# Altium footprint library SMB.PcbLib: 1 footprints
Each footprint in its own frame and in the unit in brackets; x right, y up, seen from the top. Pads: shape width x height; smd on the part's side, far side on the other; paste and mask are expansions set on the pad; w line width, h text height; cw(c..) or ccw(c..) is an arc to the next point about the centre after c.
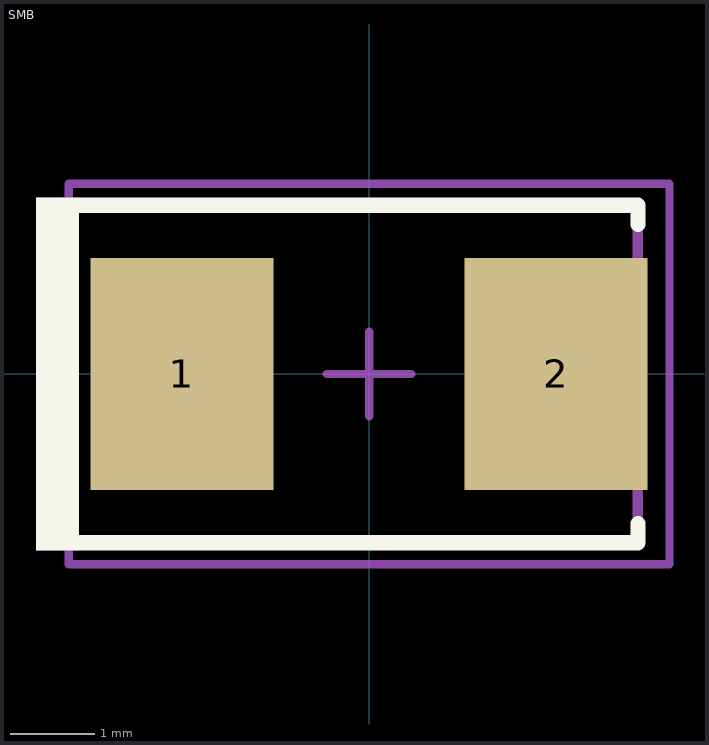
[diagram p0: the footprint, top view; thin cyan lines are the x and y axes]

## SMB [mil] "Molded Diode, 2-Leads, Body 5.4x3.6mm, IPC Medium Density, based on OnSemi component dimensions"
height 96.46
pads (2):
  rect 85x107.99 smd: 1(-87.01,0) 2(87.01,0)
Top Overlay:
  rectangle: -155,-82 -135,82
  lines w7: -142,-78.5 125,-78.5 125,-69.5 ; -142,78.5 125,78.5 125,69.5
M5 Assembly Top:
  rectangle: -155,-82 -135,82
  lines w5: -142,-78.5 125,-78.5 125,-69.5 125,69.5 125,78.5 -142,78.5
  text ".Designator" at -91,-20 h40
M15  Courtyards Top:
  lines w3.94: -19.68,0 19.69,0 ; 0,-19.69 0,19.68 ; -139.76,-88.58 -139.76,88.58 139.76,88.58 139.76,-88.58 -139.76,-88.58
3D body: height 91.35, standoff 0.6, extent -106.3,-70.86 106.3,70.87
